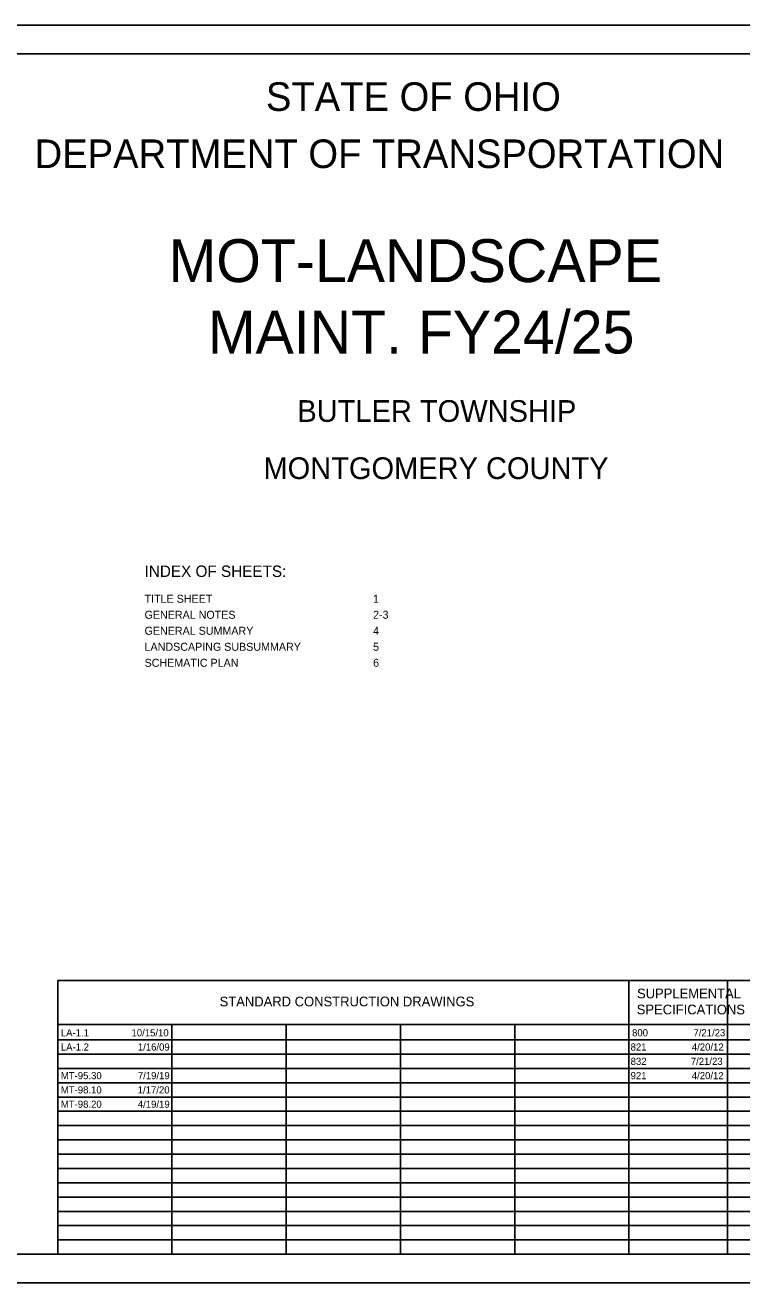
# Model space of a CAD drawing. Extents: x 8.5 to 81.5, y -1.2 to 22.4.
# Drawn here: x 57.11 to 69.65, y 0.35 to 22.35 of the extents above; entities that cross this region are included whole.
import ezdxf

# ---------------------------------------------------------------- set-up
doc = ezdxf.new("R2010")
doc.units = 0
for name, color, linetype in [('SH_Border', 7, 'Continuous'), ('SH_Cut_Line', 7, 'Continuous'), ('SH_Data', 7, 'Continuous'), ('SH_Text', 7, 'Continuous')]:
    doc.layers.add(name, color=color, linetype=linetype)

msp = doc.modelspace()

# ---------------------------------------------------------------- linework, layer by layer
at = {"layer": 'SH_Border'}
msp.add_lwpolyline([(49.026, 21.851), (81.026, 21.851), (81.026, 0.851), (49.026, 0.851)], close=True, dxfattribs=at)
at = {"layer": 'SH_Cut_Line'}
msp.add_lwpolyline([(47.526, 0.351), (81.526, 0.351), (81.526, 22.351), (47.526, 22.351)], close=True, dxfattribs=at)
at = {"layer": 'SH_Data'}
for p, q in [((57.676, 5.642), (71.126, 5.642)), ((57.676, 0.851), (57.676, 5.642)), ((67.676, 0.851), (67.676, 5.642)), ((69.401, 0.851), (69.401, 5.642)), ((57.676, 4.871), (71.126, 4.871)), ((59.676, 0.851), (59.676, 4.871)), ((61.676, 0.851), (61.676, 4.871)), ((63.676, 0.851), (63.676, 4.871)), ((65.676, 0.851), (65.676, 4.871)), ((57.676, 4.601), (71.126, 4.601)), ((57.676, 4.351), (71.126, 4.351)), ((57.676, 4.101), (71.126, 4.101)), ((57.676, 3.851), (71.126, 3.851)), ((57.676, 3.601), (71.126, 3.601)), ((57.676, 3.351), (71.126, 3.351)), ((57.676, 3.101), (71.126, 3.101)), ((57.676, 2.851), (71.126, 2.851)), ((57.676, 2.601), (71.126, 2.601)), ((57.676, 2.351), (71.126, 2.351)), ((57.676, 2.101), (71.126, 2.101)), ((57.676, 1.851), (71.126, 1.851)), ((57.676, 1.601), (71.126, 1.601)), ((57.676, 1.351), (71.126, 1.351)), ((57.676, 1.101), (71.126, 1.101))]:
    msp.add_line(p, q, dxfattribs=at)

# ---------------------------------------------------------------- texts
at = {"layer": 'SH_Text'}
for s, height, p in [('STATE OF OHIO', 0.5, (61.321, 20.851)), ('DEPARTMENT OF TRANSPORTATION', 0.5, (57.272, 19.851)), ('MOT-LANDSCAPE', 0.75, (59.617, 17.856)), ('MAINT. FY24/25', 0.75, (60.304, 16.606)), ('   BUTLER TOWNSHIP  ', 0.38, (61.448, 15.411)), ('  MONTGOMERY COUNTY ', 0.38, (60.996, 14.411)), ('INDEX OF SHEETS:', 0.2, (59.197, 12.698)), ('TITLE SHEET                         ', 0.14, (59.197, 12.247)), ('1      ', 0.14, (63.197, 12.247)), ('GENERAL NOTES                       ', 0.14, (59.197, 11.967)), ('2-3    ', 0.14, (63.197, 11.967)), ('GENERAL SUMMARY                     ', 0.14, (59.197, 11.687)), ('4      ', 0.14, (63.197, 11.687)), ('LANDSCAPING SUBSUMMARY              ', 0.14, (59.197, 11.407)), ('5      ', 0.14, (63.197, 11.407)), ('SCHEMATIC PLAN                      ', 0.14, (59.197, 11.127)), ('6      ', 0.14, (63.197, 11.127)), ('STANDARD CONSTRUCTION DRAWINGS', 0.17, (60.511, 5.187)), ('SUPPLEMENTAL', 0.17, (67.818, 5.327)), ('SPECIFICATIONS', 0.17, (67.813, 5.047)), ('LA-1.1', 0.125, (57.731, 4.663)), ('10/15/10', 0.125, (58.968, 4.663)), ('800', 0.125, (67.731, 4.663)), ('7/21/23', 0.125, (68.806, 4.663)), ('LA-1.2', 0.125, (57.731, 4.413)), ('1/16/09', 0.125, (59.079, 4.413)), ('821', 0.125, (67.706, 4.413)), ('4/20/12', 0.125, (68.777, 4.413)), ('832', 0.125, (67.706, 4.163)), ('7/21/23', 0.125, (68.759, 4.163)), ('MT-95.30', 0.125, (57.731, 3.913)), ('7/19/19', 0.125, (59.079, 3.913)), ('921', 0.125, (67.706, 3.913)), ('4/20/12', 0.125, (68.777, 3.913)), ('MT-98.10', 0.125, (57.731, 3.663)), ('1/17/20', 0.125, (59.077, 3.663)), ('MT-98.20', 0.125, (57.731, 3.413)), ('4/19/19', 0.125, (59.079, 3.413))]:
    msp.add_text(s, height=height, dxfattribs=at).set_placement(p)

doc.saveas('drawing.dxf')
